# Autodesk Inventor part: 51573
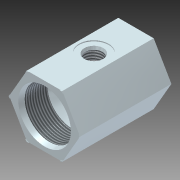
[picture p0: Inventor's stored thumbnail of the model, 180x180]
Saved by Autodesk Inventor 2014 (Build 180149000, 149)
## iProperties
Shininess: 20.0
Length Units: 11272
Angle Units: 11279
Time Units: 11290
Mass Units: 11286
Length Display Precision: 3
Angle Display Precision: 2
Company: Autodesk, Inc.
Created: 2002-09
Part Number: 51573
Project: 2039
Material: Stainless Steel 316
Description: FITTING; TE J20-J12-J6-(SS)
Document SubType Name: Modeling
Designer: Autodesk, Inc.
Density: 8.182 g/cm^3
Mass: 876.859 g
Surface Area: 239.24 cm^2
Volume: 107.169 cm^3
Appearance: Stainless Steel
Density: 0.0
Volumn: 0.0
Area: 0.0
PropertySet Name: Model Information
Control State: 0
Master: False
Checked Out: False
Last Check In By: JT
Last Check In Date: 2003-06-20
Title: FITTING; TE J20-J12-J6-(SS)
Author: Autodesk, Inc.
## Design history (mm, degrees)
sketch "Sketch1"
  geometry: L1 (-14.665, -25.4)-(-29.329, 0); L2 (-29.329, 0)-(-14.665, 25.4); L3 (-14.665, 25.4)-(14.665, 25.4); L4 (14.665, 25.4)-(29.329, 0); L5 (29.329, 0)-(14.665, -25.4); L6 (14.665, -25.4)-(-14.665, -25.4); 2 further points
  constraints: 12 end point, 1 coincident, 1 horizontal, 11 other
  dimensions: "d28" = 50.8 distance between parallel lines of L6 L3
extrude "Extrusion2" new body sketch "Sketch1" stored distance "d7" = 76.2; taper "d8" = 0 deg
sketch "Sketch2"
  geometry: L1 (28.575, 38.1)-(28.575, 37.592); L2 (28.575, 37.592)-(21.755, 37.592); L3 (21.755, 37.592)-(20.637, 33.421); L4 (20.637, 33.421)-(20.638, 14.58); L5 (20.638, 14.58)-(9.525, 3.467); L6 (9.525, 3.467)-(9.525, -10.611); L7 (9.525, -10.611)-(13.494, -14.58); L8 (13.494, -14.58)-(13.494, -34.29); L9 (13.494, -34.29)-(14.58, -37.592); L10 (14.58, -37.592)-(20.638, -37.592); L11 (20.638, -37.592)-(20.638, -38.1); L12 (0, 38.1)-(0, -38.1); L13 (28.575, 38.1)-(0, 38.1); L14 (0, -38.1)-(20.638, -38.1); L15 (-25.4, 38.1)-(0, 38.1) reference; L16 (0, 38.1)-(25.4, 38.1) reference; L17 (0, -38.1)-(-25.4, -38.1) reference; L18 (25.4, -38.1)-(0, -38.1) reference; 1 further point
  constraints: 28 end point, 4 parallel, 3 perpendicular, 1 collinear
  dimensions: "d11" = 57.15 diameter of L1 L12; "d12" = 43.5102 diameter of L2.end L12; "d13" = 15 deg angle of L4 L3; "d14" = 41.275 diameter of L4 L12; "d15" = 45 deg angle of L6 L5; "d16" = 23.0124 distance from line of L2 L4.end; "d17" = 19.05 diameter of L6 L12; "d18" = 41.275 diameter of L11 L12; "d20" = 3.302 vertical distance of L8.end L9.end; "d22" = 23.0124 distance from line of L10 L7.end; "d29" = 0.508 distance between parallel lines of L10 L14; "d30" = 0.508 distance between parallel lines of L13 L2; "d42" = 29.1592 diameter of L9.end L12; "d43" = 26.9875 diameter of L8 L12
revolve "Revolution1" sketch "Sketch2" stored, may be unused: angle "d23" = 90 deg
thread "Thread1" dims "d24" = 25.4, "d25" = 0
thread "Thread2" dims "d26" = 25.4, "d27" = 0
sketch "Sketch3"
  geometry: L1 (25.4, 38.1)-(25.4, -38.1) reference; L2 (25.4, -15.481)-(24.606, -15.481); L3 (24.606, -15.481)-(24.606, -10.998); L4 (24.606, -10.998)-(22.142, -10.319); L5 (22.142, -10.319)-(9.138, -10.319); L6 (9.138, -10.319)-(6.756, -7.937); L7 (6.756, -7.937)-(-4.417, -7.937); L8 (-4.417, -7.937)-(-4.417, -3.175); L9 (-4.417, -3.175)-(25.4, -3.175); L10 (25.4, -38.1)-(0, -38.1) reference
  constraints: 16 end point, 3 parallel, 3 perpendicular, 2 point on line
  dimensions: "d31" = 0.79375 distance between parallel lines of L1 L3; "d33" = 34.925 distance from line of L10 L8.end; "d34" = 15.6464 diameter of L3.end L9; "d35" = 24.6126 diameter of L2.start L9; "d37" = 14.2875 diameter of L5 L9; "d38" = 2.4638 horizontal distance of L3.end L4.end; "d39" = 9.525 diameter of L7 L9; "d40" = 15.4686 distance from line of L3 L5.end; "d41" = 45 deg angle of L5 L6
revolve "Revolution2" sketch "Sketch3" stored, may be unused: angle "d36" = 90 deg
thread "Thread3" dims "d44" = 25.4, "d45" = 0
body "Solid1"
